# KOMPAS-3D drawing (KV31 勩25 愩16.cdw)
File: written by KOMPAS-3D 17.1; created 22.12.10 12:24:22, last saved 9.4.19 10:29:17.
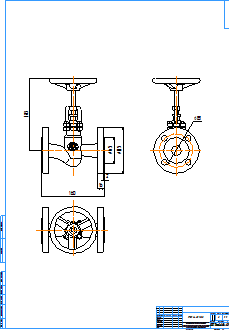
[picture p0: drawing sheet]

Title block, sheet 1: name: KV31 Ду25 Ру16; material: Внимание! Данный продукт является объектом авторского права ООО «Торговый Дом АДЛ». / Запрещается изменение, копирование, распространение / (в том числе путем копирования на другие сайты и ресурсы в Интернете) / или любое иное использование информации и объектов без предварительного / согласия правообладателя (ООО «Торговый Дом АДЛ»).; mass: 6; scale: 1:1; sheets: 1; organisation: ООО "Торговый дом АДЛ"; sheet format: A1; stored path: \\adlc.lan\data\АДЛ_ПКД\3D-модели\ADL production\Вентили ГРАНВЕНТ\KV31\KOMPAS 2D\KV31 Ду25.cdw

Views: Вид 4, Спереди 1, Проекционный вид 3
Dimensions and other numbers on the sheet: 65; 115; 2; 16; 160; 85; 183; 1:1; 1; 6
